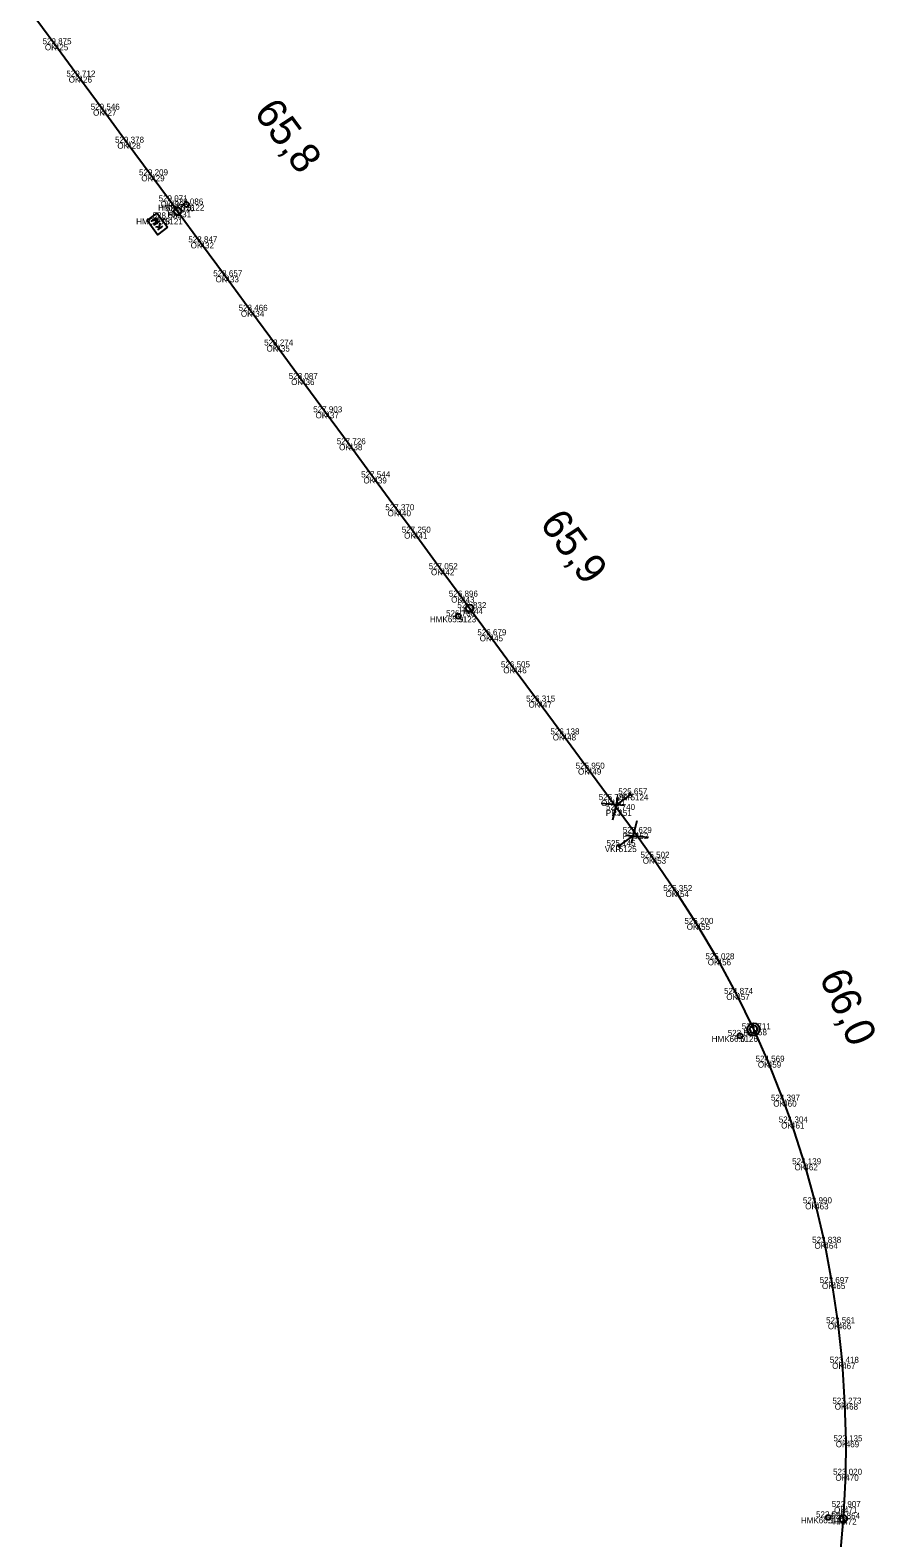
# Model space of a CAD drawing. Extents: x -621782 to -610392, y -1141853 to -1122321.
# Drawn here: x -621317 to -621148.1, y -1123220.4 to -1122919.5 of the extents above; entities that cross this region are included whole.
import ezdxf

# ---------------------------------------------------------------- set-up
doc = ezdxf.new("R2010")
doc.units = 0
for name, color, linetype in [('Vrstva 1', 7, 'Continuous'), ('Vrstva 4', 7, 'Continuous'), ('Vrstva 60', 7, 'Continuous'), ('Vrstva 61', 7, 'Continuous'), ('Vrstva 62', 7, 'Continuous'), ('Vrstva 7', 7, 'Continuous')]:
    doc.layers.add(name, color=color, linetype=linetype)

msp = doc.modelspace()

# ---------------------------------------------------------------- linework, layer by layer
at = {"layer": 'Vrstva 1'}
msp.add_lwpolyline([(-621317.05, -1122915.59), (-621312.11, -1122922.28), (-621307.36, -1122928.74), (-621302.48, -1122935.35), (-621297.64, -1122941.94), (-621292.85, -1122948.45), (-621289.03, -1122953.64), (-621287.57, -1122955.63), (-621282.99, -1122961.84), (-621278.01, -1122968.61), (-621272.95, -1122975.49), (-621267.84, -1122982.43), (-621262.91, -1122989.12), (-621258.04, -1122995.75), (-621253.34, -1123002.13), (-621248.46, -1123008.76), (-621243.64, -1123015.31), (-621240.35, -1123019.78), (-621234.97, -1123027.08), (-621230.94, -1123032.55), (-621229.25, -1123034.85), (-621225.25, -1123040.27), (-621220.53, -1123046.67), (-621215.49, -1123053.5), (-621210.65, -1123060.06), (-621205.61, -1123066.89), (-621200.99, -1123073.17), (-621199.54, -1123075.14), (-621196.2, -1123079.73), (-621192.66, -1123084.67), (-621188.11, -1123091.32), (-621183.89, -1123097.88), (-621179.69, -1123104.94), (-621175.97, -1123111.86), (-621172.52, -1123118.92), (-621169.67, -1123125.38), (-621166.59, -1123133.16), (-621165.03, -1123137.53), (-621162.36, -1123145.87), (-621160.21, -1123153.66), (-621158.36, -1123161.54), (-621156.86, -1123169.57), (-621155.68, -1123177.6), (-621154.83, -1123185.5), (-621154.32, -1123193.65), (-621154.1, -1123201.16), (-621154.18, -1123207.85), (-621154.45, -1123214.28), (-621154.6, -1123216.63), (-621155.27, -1123224.26)], dxfattribs=at)
at = {"layer": 'Vrstva 4'}
for p, q in [((-621196.79, -1123072.42), (-621197.39, -1123071.62)), ((-621198.39, -1123074.22), (-621202.99, -1123073.88)), ((-621200.61, -1123077.1), (-621199.58, -1123072.61)), ((-621197.09, -1123072.02), (-621199.92, -1123074.11)), ((-621199.54, -1123075.14), (-621196.2, -1123079.73)), ((-621195.84, -1123077.32), (-621196.94, -1123081.8)), ((-621199.44, -1123082.35), (-621196.57, -1123080.31)), ((-621198.11, -1123080.17), (-621193.51, -1123080.57)), ((-621199.73, -1123081.94), (-621199.14, -1123082.76))]:
    msp.add_line(p, q, dxfattribs=at)
at = {"layer": 'Vrstva 60'}
for p, q in [((-621312.11, -1122922.28), (-621312.11, -1122922.28)), ((-621307.36, -1122928.74), (-621307.36, -1122928.74)), ((-621302.48, -1122935.35), (-621302.48, -1122935.35)), ((-621297.64, -1122941.94), (-621297.64, -1122941.94)), ((-621292.85, -1122948.45), (-621292.85, -1122948.45)), ((-621289.03, -1122953.64), (-621289.03, -1122953.64)), ((-621285.81, -1122954.28), (-621285.81, -1122954.28)), ((-621290.12, -1122957.05), (-621290.12, -1122957.05)), ((-621287.57, -1122955.63), (-621287.57, -1122955.63)), ((-621282.99, -1122961.84), (-621282.99, -1122961.84)), ((-621278.01, -1122968.61), (-621278.01, -1122968.61)), ((-621272.95, -1122975.49), (-621272.95, -1122975.49)), ((-621267.84, -1122982.43), (-621267.84, -1122982.43)), ((-621262.91, -1122989.12), (-621262.91, -1122989.12)), ((-621258.04, -1122995.75), (-621258.04, -1122995.75)), ((-621253.34, -1123002.13), (-621253.34, -1123002.13)), ((-621248.46, -1123008.76), (-621248.46, -1123008.76)), ((-621243.64, -1123015.31), (-621243.64, -1123015.31)), ((-621240.35, -1123019.78), (-621240.35, -1123019.78)), ((-621234.97, -1123027.08), (-621234.97, -1123027.08)), ((-621230.94, -1123032.55), (-621230.94, -1123032.55)), ((-621229.25, -1123034.85), (-621229.25, -1123034.85)), ((-621231.5, -1123036.47), (-621231.5, -1123036.47)), ((-621225.25, -1123040.27), (-621225.25, -1123040.27)), ((-621220.53, -1123046.67), (-621220.53, -1123046.67)), ((-621215.49, -1123053.5), (-621215.49, -1123053.5)), ((-621210.65, -1123060.06), (-621210.65, -1123060.06)), ((-621205.61, -1123066.89), (-621205.61, -1123066.89)), ((-621200.99, -1123073.17), (-621200.99, -1123073.17)), ((-621197.09, -1123072.02), (-621197.09, -1123072.02)), ((-621199.54, -1123075.14), (-621199.54, -1123075.14)), ((-621196.2, -1123079.73), (-621196.2, -1123079.73)), ((-621199.44, -1123082.35), (-621199.44, -1123082.35)), ((-621192.66, -1123084.67), (-621192.66, -1123084.67)), ((-621188.11, -1123091.32), (-621188.11, -1123091.32)), ((-621183.89, -1123097.88), (-621183.89, -1123097.88)), ((-621179.69, -1123104.94), (-621179.69, -1123104.94)), ((-621175.97, -1123111.86), (-621175.97, -1123111.86)), ((-621172.52, -1123118.92), (-621172.52, -1123118.92)), ((-621175.22, -1123120.24), (-621175.22, -1123120.24)), ((-621169.67, -1123125.38), (-621169.67, -1123125.38)), ((-621166.59, -1123133.16), (-621166.59, -1123133.16)), ((-621165.03, -1123137.53), (-621165.03, -1123137.53)), ((-621162.36, -1123145.87), (-621162.36, -1123145.87)), ((-621160.21, -1123153.66), (-621160.21, -1123153.66)), ((-621158.36, -1123161.54), (-621158.36, -1123161.54)), ((-621156.86, -1123169.57), (-621156.86, -1123169.57)), ((-621155.68, -1123177.6), (-621155.68, -1123177.6)), ((-621154.83, -1123185.5), (-621154.83, -1123185.5)), ((-621154.32, -1123193.65), (-621154.32, -1123193.65)), ((-621154.1, -1123201.16), (-621154.1, -1123201.16)), ((-621154.18, -1123207.85), (-621154.18, -1123207.85)), ((-621157.59, -1123216.34), (-621157.59, -1123216.34)), ((-621154.45, -1123214.28), (-621154.45, -1123214.28)), ((-621154.6, -1123216.63), (-621154.6, -1123216.63))]:
    msp.add_line(p, q, dxfattribs=at)
at = {"layer": 'Vrstva 7'}
for p, q in [((-621285.84, -1122954.24), (-621285.78, -1122954.32)), ((-621290.12, -1122957.05), (-621290.63, -1122957.42)), ((-621292.02, -1122958.68), (-621290.85, -1122958.86)), ((-621291.52, -1122959.35), (-621290.52, -1122958.61)), ((-621291.28, -1122958.79), (-621291.02, -1122957.94)), ((-621231.53, -1123036.43), (-621231.47, -1123036.51)), ((-621175.24, -1123120.2), (-621175.2, -1123120.29)), ((-621157.58, -1123216.29), (-621157.59, -1123216.39))]:
    msp.add_line(p, q, dxfattribs=at)
msp.add_lwpolyline([(-621289.59, -1122958.83), (-621291.59, -1122960.3), (-621293.66, -1122957.49), (-621291.66, -1122956.02)], close=True, dxfattribs=at)
msp.add_lwpolyline([(-621291.26, -1122957.61), (-621292.26, -1122958.35), (-621291.55, -1122957.22), (-621292.83, -1122957.58), (-621291.83, -1122956.84)], dxfattribs=at)
for centre, radius in [((-621285.81, -1122954.28), 0.5), ((-621287.57, -1122955.63), 0.75), ((-621229.25, -1123034.85), 0.75), ((-621231.5, -1123036.47), 0.5), ((-621175.22, -1123120.24), 0.5), ((-621172.52, -1123118.92), 1.25), ((-621172.52, -1123118.92), 0.752), ((-621157.59, -1123216.34), 0.5), ((-621154.6, -1123216.63), 0.75)]:
    msp.add_circle(centre, radius, dxfattribs=at)

# ---------------------------------------------------------------- texts
at = {"layer": 'Vrstva 60'}
for s, p in [('425', (-621312.11, -1122923.49)), ('426', (-621307.36, -1122929.94)), ('427', (-621302.48, -1122936.55)), ('428', (-621297.64, -1122943.14)), ('429', (-621292.85, -1122949.65)), ('430', (-621289.03, -1122954.84)), ('5122', (-621285.81, -1122955.48)), ('5121', (-621290.12, -1122958.26)), ('431', (-621287.57, -1122956.83)), ('432', (-621282.99, -1122963.04)), ('433', (-621278.01, -1122969.81)), ('434', (-621272.95, -1122976.69)), ('435', (-621267.84, -1122983.63)), ('436', (-621262.91, -1122990.32)), ('437', (-621258.04, -1122996.95)), ('438', (-621253.34, -1123003.33)), ('439', (-621248.46, -1123009.96)), ('440', (-621243.64, -1123016.51)), ('441', (-621240.35, -1123020.98)), ('442', (-621234.97, -1123028.28)), ('443', (-621230.94, -1123033.75)), ('444', (-621229.25, -1123036.05)), ('5123', (-621231.5, -1123037.67)), ('445', (-621225.25, -1123041.47)), ('446', (-621220.53, -1123047.87)), ('447', (-621215.49, -1123054.7)), ('448', (-621210.65, -1123061.26)), ('449', (-621205.61, -1123068.09)), ('450', (-621200.99, -1123074.36)), ('5124', (-621197.09, -1123073.22)), ('451', (-621199.54, -1123076.33)), ('452', (-621196.2, -1123080.93)), ('5125', (-621199.44, -1123083.55)), ('453', (-621192.66, -1123085.87)), ('454', (-621188.11, -1123092.52)), ('455', (-621183.89, -1123099.08)), ('456', (-621179.69, -1123106.14)), ('457', (-621175.97, -1123113.06)), ('458', (-621172.52, -1123120.12)), ('5126', (-621175.22, -1123121.44)), ('459', (-621169.67, -1123126.58)), ('460', (-621166.59, -1123134.36)), ('461', (-621165.03, -1123138.73)), ('462', (-621162.36, -1123147.07)), ('463', (-621160.21, -1123154.86)), ('464', (-621158.36, -1123162.74)), ('465', (-621156.86, -1123170.77)), ('466', (-621155.68, -1123178.8)), ('467', (-621154.83, -1123186.7)), ('468', (-621154.32, -1123194.85)), ('469', (-621154.1, -1123202.36)), ('470', (-621154.18, -1123209.05)), ('5127', (-621157.59, -1123217.54)), ('471', (-621154.45, -1123215.48)), ('472', (-621154.6, -1123217.83))]:
    msp.add_text(s, height=1.2, dxfattribs=at).set_placement(p)
at = {"layer": 'Vrstva 61'}
for s, p in [('529.875', (-621314.57, -1122922.28)), ('529.712', (-621309.81, -1122928.74)), ('529.546', (-621304.94, -1122935.35)), ('529.378', (-621300.09, -1122941.94)), ('529.209', (-621295.3, -1122948.45)), ('529.071', (-621291.38, -1122953.64)), ('529.016', (-621290.02, -1122955.63)), ('529.086', (-621288.26, -1122954.28)), ('528.583', (-621292.58, -1122957.05)), ('528.847', (-621285.44, -1122961.84)), ('528.657', (-621280.46, -1122968.61)), ('528.466', (-621275.4, -1122975.49)), ('528.274', (-621270.29, -1122982.43)), ('528.087', (-621265.37, -1122989.12)), ('527.903', (-621260.49, -1122995.75)), ('527.726', (-621255.79, -1123002.13)), ('527.544', (-621250.91, -1123008.76)), ('527.370', (-621246.09, -1123015.31)), ('527.250', (-621242.8, -1123019.78)), ('527.052', (-621237.42, -1123027.08)), ('526.896', (-621233.39, -1123032.55)), ('526.760', (-621233.95, -1123036.47)), ('526.832', (-621231.7, -1123034.85)), ('526.679', (-621227.7, -1123040.27)), ('526.505', (-621222.99, -1123046.67)), ('526.315', (-621217.95, -1123053.5)), ('526.138', (-621213.1, -1123060.06)), ('525.950', (-621208.06, -1123066.89)), ('525.657', (-621199.54, -1123072.02)), ('525.789', (-621203.44, -1123073.17)), ('525.740', (-621201.99, -1123075.14)), ('525.629', (-621198.65, -1123079.73)), ('525.145', (-621201.89, -1123082.35)), ('525.502', (-621195.11, -1123084.67)), ('525.352', (-621190.56, -1123091.32)), ('525.200', (-621186.34, -1123097.88)), ('525.028', (-621182.14, -1123104.94)), ('524.874', (-621178.42, -1123111.86)), ('523.538', (-621177.67, -1123120.24)), ('524.711', (-621174.88, -1123118.92)), ('524.569', (-621172.12, -1123125.38)), ('524.397', (-621169.04, -1123133.16)), ('524.304', (-621167.48, -1123137.53)), ('524.139', (-621164.81, -1123145.87)), ('523.990', (-621162.66, -1123153.66)), ('523.838', (-621160.81, -1123161.54)), ('523.697', (-621159.31, -1123169.57)), ('523.561', (-621158.03, -1123177.6)), ('523.418', (-621157.28, -1123185.5)), ('523.273', (-621156.77, -1123193.65)), ('523.135', (-621156.56, -1123201.16)), ('523.020', (-621156.63, -1123207.85)), ('522.907', (-621156.9, -1123214.28)), ('522.549', (-621160.04, -1123216.34)), ('522.864', (-621157.05, -1123216.63))]:
    msp.add_text(s, height=1.2, dxfattribs=at).set_placement(p)
at = {"layer": 'Vrstva 62'}
for s, p in [('OK', (-621314.09, -1122923.49)), ('OK', (-621309.34, -1122929.94)), ('OK', (-621304.47, -1122936.55)), ('OK', (-621299.62, -1122943.14)), ('OK', (-621294.83, -1122949.65)), ('HMK65.8', (-621291.48, -1122955.48)), ('OK', (-621291.01, -1122954.84)), ('HMC65.8', (-621295.87, -1122958.26)), ('HM', (-621289.6, -1122956.83)), ('OK', (-621284.97, -1122963.04)), ('OK', (-621280, -1122969.81)), ('OK', (-621274.94, -1122976.69)), ('OK', (-621269.82, -1122983.63)), ('OK', (-621264.9, -1122990.32)), ('OK', (-621260.02, -1122996.95)), ('OK', (-621255.32, -1123003.33)), ('OK', (-621250.45, -1123009.96)), ('OK', (-621245.63, -1123016.51)), ('OK', (-621242.33, -1123020.98)), ('OK', (-621236.96, -1123028.28)), ('OK', (-621232.93, -1123033.75)), ('HM', (-621231.29, -1123036.05)), ('HMK65.9', (-621237.17, -1123037.67)), ('OK', (-621227.23, -1123041.47)), ('OK', (-621222.51, -1123047.87)), ('OK', (-621217.48, -1123054.7)), ('OK', (-621212.63, -1123061.26)), ('OK', (-621207.59, -1123068.09)), ('OK', (-621202.97, -1123074.36)), ('VKR', (-621199.9, -1123073.22)), ('PRJ', (-621202.03, -1123076.33)), ('PRJ', (-621198.68, -1123080.93)), ('VKR', (-621202.24, -1123083.55)), ('OK', (-621194.65, -1123085.87)), ('OK', (-621190.1, -1123092.52)), ('OK', (-621185.87, -1123099.08)), ('OK', (-621181.67, -1123106.14)), ('OK', (-621177.96, -1123113.06)), ('HM', (-621174.56, -1123120.12)), ('HMK66.0', (-621180.88, -1123121.44)), ('OK', (-621171.66, -1123126.58)), ('OK', (-621168.57, -1123134.36)), ('OK', (-621167.01, -1123138.73)), ('OK', (-621164.34, -1123147.07)), ('OK', (-621162.2, -1123154.86)), ('OK', (-621160.34, -1123162.74)), ('OK', (-621158.85, -1123170.77)), ('OK', (-621157.66, -1123178.8)), ('OK', (-621156.81, -1123186.7)), ('OK', (-621156.3, -1123194.85)), ('OK', (-621156.09, -1123202.36)), ('OK', (-621156.16, -1123209.05)), ('HMK66.1', (-621163.06, -1123217.54)), ('OK', (-621156.43, -1123215.48)), ('HM', (-621156.64, -1123217.83))]:
    msp.add_text(s, height=1.2, dxfattribs=at).set_placement(p)
at = {"layer": 'Vrstva 7'}
for s, rotation, p in [('65,8', 306.3787, (-621272.49, -1122935.96)), ('65,9', 306.4401, (-621215.39, -1123017.99)), ('66,0', 293.838, (-621159.46, -1123108.48))]:
    msp.add_text(s, height=6, rotation=rotation, dxfattribs=at).set_placement(p)

doc.saveas('drawing.dxf')
